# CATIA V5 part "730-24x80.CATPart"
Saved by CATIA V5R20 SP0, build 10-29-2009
Part number: 730-24x80
Definition: NONE
Nomenclature: 730-24x80
Source: Unknown
Description: 730-24x80
Bounding box of the stored display mesh (mm): x -14.941 to 14.941, y -14.5 to 14.5, z 0 to 80
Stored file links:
  C:\Users\Utente\Desktop\IO LAVORO\3D X SITO CF\X SITO\730\730-24x80.CATPart
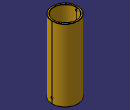
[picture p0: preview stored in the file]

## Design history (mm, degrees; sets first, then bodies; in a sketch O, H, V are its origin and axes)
Body1 "730-24x80" (main body)
  Solid1: solid without history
